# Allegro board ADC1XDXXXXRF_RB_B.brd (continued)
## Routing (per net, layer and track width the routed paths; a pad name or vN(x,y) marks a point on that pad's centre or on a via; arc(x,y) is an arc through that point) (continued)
TXD1: length 35.3
  TOP w0.14: J25.1 113.3,8.1 113.3,13.94 108.79,18.44 93.4,18.44 91.23,20.6 U2.52
USB_PWR: length 90.8
  TOP w0.305: v2(67.93,63.41) 67.93,62.38 U19.8
  TOP w0.508: C213.1 58.09,58.57 C214.1 ; C214.1 59.78,57.49 v2(59.78,57.49) ; C214.1 U19.4
  TOP w0.762: C213.1 58.08,7.78 58.78,7.09 66.77,7.09 71.56,11.88 71.56,14.55 70.83,15.28 J2.1
  BOTTOM w0.508: v2(67.93,63.41) 67.93,59.6 66.12,57.78 60.07,57.78 v2(59.78,57.49)
V_ADC: length 143.5
  TOP w0.457: J36.1 188.67,144.34 J23.3 ; J23.1 191.21,144.34 J34.1 ; J42.1 181.05,145.31 J23.9 ; J40.1 183.59,144.34 J23.7 ; J38.1 186.13,145.31 J23.5
  TOP w0.61: v1(183.36,83.31) 183.36,82.74 ; v1(189.71,83.31) 189.71,82.74 ; v1(176.05,83.18) 176.05,82.74
  TOP w0.762: L14.2 v2(160.99,167.36) C242.1 ; R58.1 191.41,82.74 v1(191.88,83.21) ; v2(160.99,162.75) 160.99,162.75 C244.1 ; C242.1 159.74,166.16 v2(159.73,166.17) ; C242.1 160.99,164.93 v2(160.99,164.93) 160.99,163.88 C244.1 ; C244.1 159.98,163.87 v2(159.98,163.88)
  PWR2 w0.356: J23.5 186.86,144.58 ; J23.5 186.86,146.05 ; J23.5 185.16,145.32 ; J23.5 185.39,146.05 ; J23.5 186.13,144.35 ; J23.5 185.39,144.58 ; J23.5 186.13,146.28 ; J23.5 187.09,145.32 ; 190.24,145.32 J23.1 ; J23.1 190.24,144.35 ; J23.1 192.17,146.28 ; J23.1 192.17,145.32 ; J23.1 191.21,144.35 ; J23.1 191.21,146.28 ; J23.1 190.24,146.28 ; J23.1 192.17,144.35 ; J23.9 181.78,146.05 ; J23.9 182.01,145.32 ; J23.9 180.31,146.05 ; J23.9 180.31,144.58 ; J23.9 181.78,144.58 ; J23.9 181.05,146.28 ; J23.9 181.05,144.35 ; J23.9 180.08,145.32 ; J23.7 183.59,146.28 ; J23.7 183.59,144.35 ; J23.7 184.32,146.05 ; J23.7 184.55,145.32 ; J23.7 182.85,146.05 ; J23.7 182.62,145.32 ; J23.7 184.32,144.58 ; J23.7 182.85,144.58 ; 187.93,144.58 J23.3 ; J23.3 188.67,146.28 ; J23.3 187.93,146.05 ; J23.3 188.67,144.35 ; J23.3 189.63,145.32 ; J23.3 187.7,145.32 ; J23.3 189.4,144.58 ; J23.3 189.4,146.05
  BOTTOM w0.254: 177.01,108.74 177.01,111.28 179.68,113.94 183.85,113.94 v1(185.34,115.44) 186.66,114.12 R222.2 186.66,109.12 186.39,108.84 186.39,107.87 R225.2 ; 177.01,108.74 R219.2 ; 177.01,108.74 R216.2 ; R210.2 178.2,83.18 v1(176.05,83.18) 175.52,83.18 R213.2 ; R204.2 188.45,82.04 v1(189.71,83.31) ; R207.2 184.38,86 184,85.62 184,83.94 v1(183.36,83.31)
  BOTTOM w0.406: C365.2 v1(185.34,115.44)
  BOTTOM w0.457: J23.7 183.59,145.31 J40.1 ; J23.3 188.67,145.31 J36.1 ; J38.1 186.13,145.31 J23.5 ; J35.1 191.21,145.31 J23.1 ; J42.1 181.05,145.31 J23.9
V_USI1: length 62.3
  BOTTOM w0.508: 155.26,165.22 155.26,165.23 158.82,168.79 165.63,168.79 183.18,186.34 186.77,186.34 189.79,189.36 J13.2 ; 155.26,165.22 155.26,156.7 J15.2 ; 155.26,165.22 J17.2
VCMO: length 135.7
  TOP w0.102: U1.C2 v1(198.57,86.67)
  SIG1 w0.152: J17.9 142.07,167.76 143.33,166.51 143.33,157.46 J15.9 ; v1(143.32,129.78) 145.79,127.31 v1(194.77,127.31)
  SIG3 w0.14: v1(143.32,129.78) 143.32,154.95 J15.9
  SIG3 w0.152: v1(198.57,86.67) 199.24,87.34 199.24,111.64 196.38,114.5 196.38,125.66 194.73,127.31 v1(194.77,127.31)
VIO_PRE: length 60.6
  TOP w0.305: U16.12 128.03,185.88 v2(128.01,185.85) ; L10.2 126.1,173.79 123.62,176.27 v2(123.62,185.85) 123.29,186.18 123.29,198.75 v2(124.21,199.66) 124.28,199.74 R106.1
  TOP w0.762: C194.1 140.22,178.98 141.96,180.72 C195.1 L2.1
  TOP w1.016: C194.1 140.23,176.66 140.23,174.9 139.12,173.79 L10.2
  BOTTOM w0.305: R105.1 v2(124.21,199.66) ; v2(128.01,185.85) v2(123.62,185.85)
WE_N: length 90.9
  TOP w0.102: U5.AA8 120.72,83.74 v1(120.71,83.74)
  TOP w0.14: v1(85.73,25.69) U2.41
  SIG1 w0.152: v1(85.73,25.69) 89.3,29.26 89.3,58.35 91.78,60.83 v1(91.78,81.22)
  BOTTOM w0.152: v1(120.71,83.74) 120.7,83.74 120.22,83.26 119.91,83.26 119.91,83.26 119.51,83.26 119.5,83.26 118.91,83.26 118.91,83.26 118.51,83.26 118.5,83.26 117.91,83.26 117.91,83.26 117.51,83.26 117.5,83.26 116.91,83.26 116.91,83.26 116.51,83.26 116.5,83.26 114.91,83.26 114.9,83.26 114.5,83.26 114.5,83.26 111.9,83.26 111.9,83.26 111.5,83.26 111.5,83.26 93.82,83.26 v1(91.78,81.22)
N16663533: length 50.8
  TOP w0.102: J28.3 192.81,3.71 ; J27.3 211.2,14.38
  TOP w0.14: 192.81,3.71 v1(192.81,5.64) ; 211.2,14.38 v1(209.27,14.38)
  SIG1 w0.152: v1(209.27,14.38) 182.64,14.38 182.38,14.12 182.38,12.53 182.66,12.26 192.16,12.26 192.81,11.61 v1(192.81,5.64)
N16663537: length 88.9
  TOP w0.102: J30.3 v1(159.44,5.64) ; J29.3 v1(209.27,43.77)
  SIG1 w0.102: v1(209.27,43.77) 209.27,38.46 208.91,38.1 205.68,38.1 203.62,36.04 203.62,21.84 202.22,20.44 168.87,20.44 165.21,16.78 165.21,5.84 165.01,5.64 v1(159.44,5.64)
N16663541: length 88.9
  TOP w0.102: J32.3 v1(171.25,5.64) ; J31.3 v1(209.27,31.95)
  SIG1 w0.102: v1(171.25,5.64) 165.63,5.64 165.41,5.85 165.41,16.7 168.96,20.24 202.31,20.24 203.82,21.75 203.82,35.96 205.76,37.9 208.9,37.9 209.27,37.53 v1(209.27,31.95)
N16721567: length 33.4
  TOP w0.14: J2.3 64.94,15.4 64.94,22.44 77.76,35.27 U2.18
N16721659: length 31.6
  TOP w0.14: U2.19 77.7,34.77 65.23,22.3 65.23,15.54 65.48,15.28 J2.2
N16722721: length 46.3
  BOTTOM w0.229: C69.2 76.63,5.51 ; C69.2 75.72,5.51 ; C69.2 77.55,5.51 ; C69.2 77.55,3.68 ; C69.2 76.63,3.68 ; C69.2 75.72,4.6 ; C69.2 77.55,4.6 ; C69.2 75.72,3.68 ; 75.72,6.07 R24.2 ; R24.2 75.72,6.99 ; R24.2 75.72,7.9 ; R24.2 77.55,7.9 ; R24.2 76.63,7.9 ; R24.2 77.55,6.99 ; R24.2 76.63,6.07 ; R24.2 77.55,6.07
  BOTTOM w0.356: 73.03,9.28 J2.6 ; J2.6 75.61,9.28 ; J2.6 75.61,11.86 ; J2.6 74.32,8.82 ; J2.6 73.03,11.86 ; J2.6 76.07,10.57 ; J2.6 72.57,10.57 ; J2.6 74.32,12.33 ; J2.5 64.03,10.57 ; J2.5 60.99,11.86 ; J2.5 62.28,8.82 ; J2.5 63.57,9.28 ; J2.5 62.28,12.33 ; J2.5 63.57,11.86 ; J2.5 60.53,10.57 ; J2.5 60.99,9.28
N16727306: length 5.7
  TOP w0.14: R23.1 77.25,26.77 U2.35
N16769321: length 22.8
  TOP w0.305: C164.1 108,195.87 108.11,195.76 U13.15
  TOP w0.762: L5.2 v2(102.59,184.32) 102.59,193.95 104.51,195.86 106.28,195.86 C164.1
  BOTTOM w0.762: D2.2 v2(102.59,184.32)
N16769692: length 3.6
  TOP w0.305: U13.2 108.11,187.6 107.71,187.2 106.74,187.2 106.58,187.04 C175.1
N16769839: length 5.7
  TOP w0.305: U13.1 104.97,188.63 R89.2 v2(104.97,187.31) R88.2
  BOTTOM w0.305: C178.1 v2(104.97,187.31)
N16770680: length 1.2
  TOP w0.305: U13.16 C164.2
N16772680: length 3.5
  TOP w0.305: U13.4 109.41,187.47 v1(109.72,187.16) C161.1
  BOTTOM w0.305: v1(109.72,187.16) 109.72,187.16 R82.1
N16798185: length 3.2
  TOP w0.305: C190.1 136.39,193.32 C188.2 134.87,193.32 U16.1
N16802160: length 30.8
  TOP w0.102: U5.G16 129.22,98.26 v1(129.72,98.75)
  TOP w0.14: v1(127.18,116.09) 126.72,116.56 117.85,116.56 117.46,116.17 117.46,115.4 R40.2
  SIG1 w0.152: v1(127.18,116.09) 129.29,113.98 129.29,107.5 128.22,106.43 128.22,102.31 129.21,101.32 129.21,99.26 v1(129.72,98.75)
N16802193: length 75.2
  TOP w0.102: U5.H13 v1(126.71,96.75) ; v1(165.48,58.07) 164.74,58.07 U8.6
  SIG2 w0.102: v1(165.48,58.07) 166.54,58.07 166.71,58.24 166.71,64.61 153.65,77.67 133.8,77.67 133.12,78.35 133.12,78.56 133.12,96.91 132.88,97.15 127.12,97.15 126.72,96.75 v1(126.71,96.75)
  BOTTOM w0.102: C75.2 166.62,58.48 166.47,58.33 165.74,58.33 v1(165.48,58.07)
N16802234: length 11.7
  TOP w0.102: U5.G14 127.22,98.26 v1(127.71,98.75)
  TOP w0.152: v1(127.74,106.97) R31.2
  SIG2 w0.152: v1(127.74,106.97) 128.21,106.49 128.21,99.25 v1(127.71,98.75)
N16802239: length 21.8
  TOP w0.102: v1(127.71,85.74) 127.22,86.24 U5.W14 ; U5.Y15 128.22,85.25 v1(128.71,85.74) 128.22,86.24 U5.W15
  TOP w0.14: R38.2 132.99,70.15 129.92,73.22 129.92,75.42 130.22,75.72 130.22,76.94 129.72,77.45 v1(129.72,77.45)
  SIG1 w0.152: v1(127.71,85.74) v1(128.71,85.74) 128.72,85.74 129.23,85.23 129.23,77.94 v1(129.72,77.45)
N16803121: length 3.8
  TOP w0.305: R103.1 130.23,195.82 C191.2 130.27,195.2 129.98,194.91 U16.6
N16805297: length 11.1
  TOP w0.305: U16.7 129.33,194.89 128.98,195.24 C191.1 128.85,195.91 C202.1 128.28,197.08 127.88,197.47 127.88,198.06 ; R106.2 127.81,199.74 v1(127.88,199.66) 127.88,198.06 127.88,198.06 ; 127.88,198.06 R107.2
  BOTTOM w0.305: R105.2 v1(127.88,199.66)
N16805320: length 1.8
  TOP w0.14: R53.1 Y2.3
N16807514: length 1.4
  TOP w0.305: C202.2 128.85,198.37 R103.2
N16809137: length 4.6
  TOP w0.305: U16.8 128.68,194.65 127.97,195.36 127.97,196.13 127.62,196.48 R108.2
N16815468: length 2.7
  TOP w0.305: U16.9 128.03,194.43 127.53,194.94 126.68,194.94 C206.1
N16819191: length 1.4
  TOP w0.305: U16.20 C189.1
N16819385: length 30.7
  TOP w0.305: 131.28,183.56 131.28,182.91 L10.1 ; 131.28,183.56 131.89,183.56 131.93,183.6 131.93,185.1 ; 131.28,183.56 U16.17 ; 131.93,185.1 134.38,185.1 134.66,185.38 C189.2 ; 131.93,185.1 U16.18
  TOP w0.762: v2(130.66,179.07) 130.66,182.27 L10.1 135.64,182.27 v2(136.73,181.18)
  BOTTOM w0.762: v2(130.66,179.07) 130.66,180.17 131.67,181.18 D4.2 v2(136.73,181.18)
N16821177: length 16.7
  TOP w0.305: v2(129.22,185.2) 129.98,185.96 U16.15 ; U16.16 130.63,185.2 v2(130.51,185.07)
  BOTTOM w0.508: v2(129.22,185.2) 129.2,185.2 128.59,184.58 127.69,184.58 126.84,183.73 126.84,181.25 D4.1 127.16,181.44 128.7,181.44 130.51,183.24 v2(130.51,185.07)
N16824930: length 1.4
  TOP w0.305: C205.1 125.98,187.38 U16.11
N16831687: length 18.3
  TOP w0.762: 143.38,184.82 147.82,184.82 152.48,180.15 C198.1 C196.1 U17.2
N16860475: length 1.5
  TOP w0.305: U18.1 C218.1
N16862731: length 5.5
  TOP w0.305: C212.1 R109.2 ; C212.1 v2(202.21,202.31) ; C212.1 U18.6
  BOTTOM w0.305: v2(202.21,202.31) C212.1
N16862763: length 10.5
  TOP w0.508: U18.5 202.19,200.11 C212.2 202.21,200.08 v2(202.21,198.46) C209.1
  TOP w0.762: L3.1 C209.1
  BOTTOM w0.508: R110.1 202.21,199.95 v2(202.21,198.46)
N16864683: length 9.2
  TOP w0.14: J163.3 R180.1
N16864708: length 2.8
  TOP w0.305: T2.4 200.9,126.09 201.05,125.93 C342.1
N16864710: length 2.8
  TOP w0.305: C341.1 202.06,125.93 202.22,126.09 T2.6
N16864734: length 11.4
  TOP w0.14: R180.2 201.56,130.51 C343.1
N16865152: length 13
  TOP w0.14: v1(194.51,159.79) 194.51,159.56 194.29,159.34 U12.30
  SIG1 w0.14: v1(194.51,159.79) 191.85,162.46 J158.2
N16865229: length 8.6
  TOP w0.14: J161.2 185.33,153.14 189.56,153.14 190.03,153.61 U12.10
N16865231: length 9.2
  TOP w0.14: J160.2 185.29,155.71 185.29,154.99 186.56,153.72 189.31,153.72 189.85,154.26 U12.9
N16865233: length 11.1
  TOP w0.14: J159.2 185.85,157.69 185.85,155.3 186.99,154.15 189.18,154.15 189.79,154.76 U12.8
N16865299: length 9
  TOP w0.14: J162.2 184.03,152.7 191.41,152.7 191.79,153.08 U12.11
N16865342: length 6.4
  TOP w0.14: C2_LF.1 197.43,157.56 196.64,156.76 U12.24 ; C2_LF.1 198.27,158.37 C1_LF.1 ; C2_LF.1 196.98,156.26 U12.23
N16865346: length 1.7
  TOP w0.14: R73.2 199.72,157.53 C2_LF.2 199.67,157.58 R2_LF.2
N16865743: length 6.8
  TOP w1.016: Y3.4 198.65,171.08 C138.2 C137.2 C240.1 R65.2
N16865780: length 1.5
  TOP w0.14: C321.2 199.49,154.42 R196.1 199.48,153.73 R195.2
N16865782: length 11.1
  TOP w0.14: R180.3 199.47,142.74 R197.1 199.47,152.05 R195.1
N16906306: length 4.3
  TOP w0.14: C139.1 R69.1 R68.1 193.83,166.65 R66.1
N16906312: length 2.1
  TOP w0.14: C139.2 193.79,160.98 U12.31
N16907733: length 22.6
  TOP w0.305: C165.1 113.34,195.87 111.5,195.87 111.36,195.73 U13.10
  TOP w0.762: C165.1 114.71,195.87 116.96,193.62 v2(116.96,184.56) 116.97,184.55 L6.1
  BOTTOM w0.762: v2(116.96,184.56) 117.01,184.51 D3.2
N16907748: length 2.4
  TOP w0.305: C176.1 111.44,187.14 111.36,187.22 111.36,188.63 U13.7
N16907762: length 4.6
  TOP w0.305: U13.8 112.01,188.63 R90.2 v2(113.33,187.31) R91.2
  BOTTOM w0.305: C179.1 v2(113.33,187.31)
N16907804: length 1.3
  TOP w0.305: U13.9 C165.2
N16911166: length 2.1
  TOP w0.254: C154.1 194.79,151.89 U12.17
N16911176: length 2.5
  TOP w0.14: U12.21 198.46,155.26 C321.1
N16911178: length 1.4
  TOP w0.254: C154.2 R78.2
N16911299: length 2.5
  TOP w0.254: C155.2 195.29,152.79 U12.18
N16911375: length 1.2
  TOP w0.254: C142.2 R70.1
N16911379: length 2.1
  TOP w0.254: U12.28 195.29,160.92 C142.1
N16911437: length 2.2
  TOP w0.254: U12.36 191.29,160.65 C143.1
N16911467: length 2.4
  TOP w0.14: U12.32 193.29,159.51 192.46,160.35 C140.2
N16911489: length 2.7
  TOP w0.254: C149.2 188.88,155.76 U12.6
  TOP w0.508: C149.2 v1(188.82,154.84)
N16911507: length 4.2
  TOP w0.254: U12.26 196.29,157.76 196.77,158.24 196.77,159.59 197.51,160.32 C147.2
N16911511: length 1.2
  TOP w0.254: C147.1 R71.1
N16915941: length 3.2
  TOP w0.14: Y3.3 R67.1 193.83,168.12 R66.2
N16917380: length 5.4
  TOP w0.14: v1(197.36,158.55) 197.18,158.37 197.18,157.91 196.53,157.26 U12.25
  BOTTOM w0.14: v1(197.36,158.55) v1(200.58,158.55)
N16922604: length 1.5
  TOP w0.14: T2.2 201.56,129.48 C343.2
N16954745: length 11.1
  TOP w0.508: C223.1 185.81,198.47 v2(185.82,198.48) C226.2 185.79,200.3 U20.5
  TOP w0.762: L12.1 C223.1
  BOTTOM w0.305: R118.1 185.82,200.12 v2(185.82,198.48)
N16954757: length 1.6
  TOP w0.305: U20.1 C227.1
N16954773: length 5.2
  TOP w0.305: U20.6 C226.1 185.82,202.43 v2(185.79,202.46) 185.8,202.47 R117.2
  BOTTOM w0.305: R118.2 185.79,201.57 v2(185.79,202.46)
N17041129: length 50.3
  TOP w0.14: v1(101.07,42.27) U2.99
  TOP w0.152: v1(122.08,16.05) R18.2
  TOP w0.203: R18.2 U3.3
  SIG1 w0.152: v1(122.08,16.05) 116.78,21.35 v1(116.78,42.27)
  SIG3 w0.152: v1(101.07,42.27) v1(116.78,42.27)
N17122999: length 2.7
  TOP w0.152: R20.2 U4.1
N17127467: length 3.4
  TOP w0.14: R16.1 102.4,35.27 U2.85
N17138281: length 37
  TOP w0.305: v2(84.72,39.29) 84.7,39.27 U2.10 ; U2.17 v2(84.72,35.77)
  TOP w1.016: L1.1 C64.1 75.07,50.51 v2(75.08,50.5)
  BOTTOM w0.508: v2(84.72,39.29) 85.79,39.29 C66.1 87.75,39.13 ; v2(84.72,35.77) 84.72,35.78 C65.1 87.51,35.78 87.75,36.02
  BOTTOM w1.016: v2(75.08,50.5) 76.34,49.24 81.34,49.24 87.75,42.82 87.75,36.02
N17209995: length 35.7
  BOTTOM w1.27: L9.2 66.26,182.06 85.39,201.19 J12.2
N17221364: length 40
  TOP w0.305: R99.2 62.18,175.26 72.08,175.26 74.63,177.82
  TOP w0.762: L4.1 C157.1
  TOP w1.524: C157.1 74.63,177.82 70.46,181.99 SW2.2
N17237535: length 25.4
  TOP w0.152: v1(103.05,33.63) 102.73,33.95 100.33,33.95 100.15,33.77 U2.82 ; v1(114.12,18.58) LD11.2
  BOTTOM w0.152: v1(103.05,33.63) 103.05,29.65 v1(114.12,18.58)
N17238039: length 2.1
  TOP w0.305: LD11.1 R142.1
N17247885: length 3.3
  TOP w0.305: R99.1 LD10.1
N17271500: length 1.5
  TOP w0.305: U15.1 C186.1
N17271514: length 5.2
  TOP w0.305: R97.2 R98.2 C185.1 U15.6
N17272516: length 7.4
  TOP w0.508: U22.5 170.5,200.14 C233.2
  TOP w0.635: C233.2 v2(170.52,198.99)
  TOP w0.762: v2(170.52,198.99) 170.19,198.99 169.69,198.49 C230.1 L13.1
  BOTTOM w0.508: v2(170.52,198.99) 170.52,199.99 R125.1
N17272520: length 1.5
  TOP w0.305: U22.1 C234.1
N17272540: length 5.5
  TOP w0.305: R124.2 v2(170.52,202.38) C233.1 U22.6
  BOTTOM w0.305: v2(170.52,202.38) 170.52,201.42 R125.2
N17383940: length 12.2
  TOP w0.14: U2.11 81.55,38.77 79.2,41.12 78.21,41.12 77.77,41.55 Y1.1
  TOP w0.152: C70.1 Y1.1
N17383990: length 12
  TOP w0.14: U2.12 81.62,38.27 79.07,40.82 78.21,40.82 77.77,40.39 Y1.2
  TOP w0.152: C71.1 Y1.2
N17384219: length 6.5
  TOP w0.14: TP2.1 82.98,50.25 U2.1
N17400918: length 1.5
  TOP w0.305: U23.20 95.05,159.89 R92.2
N17401691: length 3.5
  TOP w0.305: R93.2 92.79,168.15 91.65,167 91.65,165.82 91.64,165.82 U23.4
N17402468: length 1.6
  TOP w0.305: U23.1 93.59,165.83 C235.1
N17411980: length 1.5
  TOP w0.305: R93.1 92.79,171.83 C236.1
N17414023: length 3.3
  TOP w0.203: U3.4 SW1.1
N17421515: length 4.9
  TOP w0.305: C237.1 94.26,157.43 93.89,157.8 92.7,157.8 92.3,158.2 92.3,159.4 92.29,159.4 U23.18
N17425568: length 5.5
  TOP w0.305: U23.2 92.94,166.19 92.95,166.2 92.95,167.3 94.32,168.67 95.27,168.67 R94.2 R95.2
N17434478: length 43.4
  TOP w0.305: U23.8 89.04,166.23 89.05,166.23 89.05,167.95 ; 89.05,167.95 D1.2 ; 89.05,167.95 89.65,167.95 89.7,167.91 89.7,166.15 89.69,166.15 U23.7 ; v1(92.13,154.4) 92.13,154.41 C238.2 ; U23.13 89.04,159.07 89.05,159.06 89.05,158.74 v2(89.36,158.42) 89.7,158.75 89.7,159.3 89.69,159.3 U23.14
  TOP w0.762: 79.98,166.63 v2(79.98,166.6) L7.1 ; 79.98,166.63 D5.2 ; 79.98,166.63 82.9,166.63 D1.2
  BOTTOM w0.305: v1(92.13,154.4) 92.13,155.66 v2(89.36,158.42)
  BOTTOM w1.016: v2(89.36,158.42) 81.19,166.6 v2(79.98,166.6)
N17462336: length 40.7
  TOP w0.305: R94.1 96.1,167.25 96.47,166.88 96.47,152.81 95.35,151.69 88,151.69 86.23,153.46 79.99,153.46 L7.2
  TOP w0.762: L7.2 C239.1 C197.1 L8.1
N17658689: length 1
  TOP w0.102: U1.K2 v1(198.64,95.49)
N17658690: length 1.8
  TOP w0.102: v1(194.83,98.15) 194.87,98.15 U1.M4
  BOTTOM w0.305: C79.1 v1(194.83,98.15)
N17663170: length 1
  TOP w0.102: U1.L2 v1(198.64,96.76)
N17675090: length 1.8
  TOP w0.102: U1.J4 194.83,95.49 v1(194.83,95.53)
  BOTTOM w0.305: C72.1 v1(194.83,95.53)
N17676120: length 17.7
  TOP w0.102: 199.79,86 U1.B1
  TOP w0.14: TP1.1 206.58,73.56 206.58,79.22 199.79,86
N17676520: length 5.9
  TOP w0.102: v1(197.29,86.64) 196.71,87.23 196.71,87.25 196.7,87.25 U1.C3
  BOTTOM w0.102: R12.1 201.19,87.18 197.84,87.18 v1(197.29,86.64)
N17676524: length 5.8
  TOP w0.102: U1.D3 196.74,88.54 v1(197.34,87.95)
  BOTTOM w0.102: v1(197.34,87.95) 197.9,87.39 201.19,87.39 R12.2
N17676530: length 10.7
  TOP w0.102: R7.1 207.15,85.5 207.15,85.93 207.1,85.98 205.45,85.98 203.61,87.81 199.27,87.81 199.19,87.73 199.19,87.46 199.24,87.42 U1.C1
N17676534: length 10.8
  TOP w0.102: U1.D2 198.45,88.07 203.71,88.07 205.55,86.23 R7.2
N17751700: length 7.2
  BOTTOM w1.524: L9.4 J21.1
N17752133: length 44.8
  BOTTOM w1.524: J21.2 74.73,167.44 65.13,167.44 63.17,169.39 63.17,183.13 SW2.3
N17824195: length 30.1
  BOTTOM w1.27: L9.1 68.8,178.84 68.8,181.09 82.91,195.2 90.81,195.2
N17846912: length 1.8
  TOP w0.102: v1(197.35,104.42) 196.72,105.05 U1.U3
  BOTTOM w0.152: R9.2 197.41,104.36 v1(197.35,104.42)
N17848835: length 1.8
  TOP w0.102: U1.V3 196.72,106.32 v1(197.34,105.7)
  BOTTOM w0.152: v1(197.34,105.7) 197.43,105.78 R25.2
N17849798: length 2.3
  TOP w0.102: U1.Y3 196.69,108.86 v1(196.1,109.46)
  BOTTOM w0.152: v1(196.1,109.46) 196.11,109.46 196.51,109.85 196.51,110.68 R2.2
N17850762: length 3.8
  TOP w0.102: U1.W4 195.45,107.59 v1(196.03,108.18)
  BOTTOM w0.152: R3.2 195.39,110.32 195.39,108.82 v1(196.03,108.18)
N17851727: length 1.7
  TOP w0.102: U1.B3 196.11,86.6 v1(196.09,86.6)
  BOTTOM w0.14: R4.2 196.1,86.6 v1(196.09,86.6)
N17852693: length 5.9
  TOP w0.102: v1(196.06,106.95) 195.44,106.32 U1.V4
  BOTTOM w0.14: 194.17,109.25 195.19,108.22 195.2,108.22 196.06,107.36 v1(196.06,106.95)
  BOTTOM w0.152: R5.2 193.44,110.73 193.44,110.17 193.56,110.05 193.86,110.05 194.17,109.74 194.17,109.25
N17853660: length 7.9
  TOP w0.102: U1.V5 194.18,106.32 v1(194.76,106.91)
  SIG1 w0.152: v1(191.86,111.25) 192.94,111.25 194.76,109.43 v1(194.76,106.91)
  BOTTOM w0.14: v1(191.86,111.25) R6.2
N17854628: length 3.1
  TOP w0.102: U1.A4 195.43,84.73 v1(196.09,84.07)
  BOTTOM w0.14: v1(196.09,84.07) 196.09,83.34 196.46,82.96 197.31,82.96 R8.2
N18005197: length 2.3
  TOP w0.762: L14.1 J22.2
N18092594: length 7.2
  TOP w0.14: U2.113 92.23,52.67 92.2,52.7
N18092628: length 7.6
  TOP w0.14: 93.7,52.7 93.7,52.7 93.7,52.01 92.73,51.04 U2.112
N18102458: length 4.3
  TOP w0.14: R17.1 102.4,31.6 102.07,31.27 U2.77
N18106734: length 13.2
  TOP w0.305: 160.15,180.92 161.11,180.92 v2(161.12,180.91)
  TOP w0.762: 160.15,180.91 C201.1 160.15,178.56 160.99,177.72 C248.1 J22.1 ; 160.15,180.91 U17.4 ; 160.15,180.91 v2(161.12,180.91) C247.1
  BOTTOM w0.508: v2(161.12,180.91) 161.38,181.17 161.9,181.17 R149.1
N18113304: length 7.2
  TOP w0.762: 162.99,182.98 161.85,182.98 U17.5 v2(162.99,183.14) 162.99,182.98 ; 162.99,182.98 162.99,181.84 163.52,181.32 C247.2
  BOTTOM w0.508: 162.99,182.74 R149.2 ; 162.99,182.74 163.87,182.74 163.96,182.65 ; 162.99,182.74 v2(162.99,183.14)
N18167238: length 17.1
  TOP w0.508: 69.99,56.85 C219.2 69.96,58.57 U19.5 67.93,56.85 ; 69.99,56.85 67.93,56.85 ; 69.99,56.85 72.91,56.85 73.09,57.03 R112.1 ; 67.93,56.85 C215.1
  TOP w0.762: C215.1 66,53.75 L11.1
N18167362: length 1.6
  TOP w0.305: U19.1 C220.1
N18167368: length 5.2
  TOP w0.508: U19.6 C219.1 R111.2 R112.2
N18175634: length 19.7
  TOP w0.305: U29.5 81.48,192.23 C267.1 v2(81.48,189.73) 81.48,188.58 U21.1 79.4,188.57 79.14,188.32 79.14,186.92 79.4,186.66 U21.3
  BOTTOM w0.305: R122.2 R121.2 R120.2 84.96,189.73 v2(81.48,189.73)
N18175719: length 5.6
  TOP w0.305: U21.6 85.16,188.57 86.75,190.16 89.01,190.16 J14.1
N18175721: length 5
  TOP w0.305: J14.3 89.01,187.62 U21.5
N18175723: length 5.6
  TOP w0.305: U21.4 85.43,186.66 87.01,185.08 J14.5
N18175776: length 1.6
  TOP w0.305: C266.1 81.47,194.84 U29.4
N18581058: length 6.4
  BOTTOM w0.635: J157.1 21.03,122.07 FMC.K40 FMC.J39
N18581183: length 15.4
  BOTTOM w0.635: FMC.G39 FMC.H40 16.51,121.13 ; 16.51,121.13 15.01,121.13 FMC.F40 FMC.E39 ; 16.51,121.13 17.55,121.13 21.03,124.61 J157.2
N19099019: length 2.7
  TOP w0.102: v1(194.16,82.89) 194.16,82.9 U1.A5
  BOTTOM w0.14: v1(194.16,82.89) R127.2
N19100077: length 2
  TOP w0.102: U1.D6 193.51,89.17 v1(193.51,89.22)
  BOTTOM w0.152: R128.2 193.51,89.83 v1(193.51,89.22)
N19255100: length 5.9
  TOP w0.14: U24.2 206.94,129.61 207.18,129.84 J19.3
N19265006: length 2
  TOP w0.152: U24.7 206.94,123.31 v1(207.34,122.91)
  BOTTOM w0.102: v1(207.34,122.91) R131.1
N19266083: length 2
  TOP w0.152: v1(205.89,122.91) 206.29,123.31 U24.6
  BOTTOM w0.102: v1(205.89,122.91) R129.1
N19380996: length 2.6
  TOP w0.14: U24.3 206.29,129.76 206.19,129.86 205.76,129.86 205.64,129.75 U24.4
N20455301: length 6.9
  TOP w0.14: R83.3 149.17,40.23 150.29,41.35 U14.12
N20455532: length 6.7
  TOP w0.14: R83.1 149.35,43.64 150.14,42.85 U14.9
N21058732: length 102.6
  TOP w0.102: v1(132.72,80.74) 132.22,81.24 U5.AD19
  TOP w0.14: R44.1 168.52,132.36 v1(168.52,131.88)
  SIG1 w0.152: v1(133.95,75.89) v1(161.2,75.89)
  SIG3 w0.152: v1(132.72,80.74) 132.7,80.74 132.21,80.25 132.21,77.62 v1(133.95,75.89)
  BOTTOM w0.14: v1(161.2,75.89) 161.2,116.37 168.52,123.69 v1(168.52,131.88)
N21059382: length 97.3
  TOP w0.102: U5.AC19 132.22,82.24 v1(132.72,81.74)
  TOP w0.14: v1(167.75,131.11) 167.75,134.14 R45.1
  SIG1 w0.152: v1(160.29,77.27) 140.27,77.27 136.29,81.24 133.22,81.24 132.83,81.63 132.83,81.63 v1(132.72,81.74)
  BOTTOM w0.14: v1(160.29,77.27) 160.29,97.36 160.73,97.81 160.73,99.01 160.29,99.45 160.29,116.53 167.75,123.99 v1(167.75,131.11)
N21060033: length 102
  TOP w0.102: v1(132.72,83.74) 132.22,84.24 U5.AA19
  TOP w0.14: v1(166.99,131.88) 166.99,135.92 R46.1
  SIG1 w0.152: v1(159.43,76.34) 134.2,76.34 132.22,78.32 132.22,83.25 v1(132.72,83.74)
  BOTTOM w0.14: v1(159.43,76.34) 159.43,97.06 158.69,97.81 158.69,98.7 159.43,99.45 159.43,116.73 166.99,124.29 v1(166.99,131.88)
N21060685: length 98.7
  TOP w0.102: U5.AA20 133.22,84.24 v1(133.72,83.74)
  TOP w0.14: v1(166.22,131.11) 166.22,137.69 R26.1
  SIG1 w0.152: v1(134.43,76.81) v1(158.62,76.81)
  SIG3 w0.152: v1(134.43,76.81) 133.23,78.02 133.23,83.26 133.71,83.74 v1(133.72,83.74)
  BOTTOM w0.14: v1(166.22,131.11) 166.22,124.59 158.62,116.99 158.62,99.39 158.24,99.02 158.24,97.49 158.62,97.12 v1(158.62,76.81)
N21061338: length 104.3
  TOP w0.102: v1(130.72,84.74) 130.22,85.24 U5.Y17
  TOP w0.14: v1(165.46,131.88) 165.46,138.51 R27.1
  SIG1 w0.152: v1(130.73,76.69) 132.44,74.97 v1(157.78,74.97)
  SIG3 w0.152: v1(130.73,76.69) 130.22,77.2 130.22,84.25 v1(130.72,84.74)
  BOTTOM w0.14: v1(157.78,74.97) 157.78,117.22 165.46,124.89 v1(165.46,131.88)
N21061992: length 101.8
  TOP w0.102: U5.AA17 130.22,84.24 v1(130.72,83.74)
  TOP w0.14: v1(164.7,131.11) 164.7,136.73 R28.1
  SIG1 w0.152: v1(157.1,75.43) 132.81,75.43 v1(131.72,76.52)
  SIG3 w0.152: v1(131.72,76.52) 131.22,77.01 131.22,83.23 130.72,83.73 v1(130.72,83.74)
  BOTTOM w0.14: v1(164.7,131.11) 164.7,125.2 157.1,117.6 v1(157.1,75.43)
N21062647: length 92.6
  TOP w0.102: U5.AB20 133.22,83.24 v1(133.72,82.74)
  TOP w0.14: v1(163.93,131.88) 163.93,134.96 R113.1
  SIG3 w0.152: v1(156.29,78.17) 135.23,78.17 135.09,78.31 135.09,78.31 134.22,79.18 134.22,82.25 133.73,82.74 v1(133.72,82.74)
  BOTTOM w0.14: v1(163.93,131.88) 163.93,125.5 156.29,117.86 v1(156.29,78.17)
N21063303: length 86.7
  TOP w0.102: v1(133.72,81.74) 133.22,82.24 U5.AC20
  TOP w0.14: R114.1 155.56,137.19 v1(155.56,126.5)
  SIG1 w0.152: v1(133.72,81.74) 133.73,81.74 134.23,82.24 138.12,82.24 142.65,77.72 v1(155.57,77.72)
  BOTTOM w0.14: v1(155.56,126.5) 155.57,126.49 v1(155.57,77.72)
N21827542: length 1.7
  TOP w0.102: R136.1 201.52,179.62 201.78,179.87 U25.7
N21827567: length 1.7
  TOP w0.102: U25.6 201.73,180.52 201.52,180.73 201.52,180.97 201.53,180.97 R134.1
N21827581: length 4.2
  TOP w0.14: U25.2 207.81,179.87 J26.3
N21832116: length 2.4
  TOP w0.203: U25.3 207.8,180.52 208.64,180.52 208.74,180.62 208.74,181.03 208.6,181.17 U25.4
N21933562: length 3.7
  TOP w0.14: R126.1 157.58,58.98 159.11,58.98 160.02,58.07 U8.9
N23828730: length 11.2
  TOP w0.102: 124.71,80.75 125.21,81.24 U5.AD12
  TOP w0.14: 124.71,80.75 124.71,70.26 R53.2
N200444310: length 2.4
  TOP w0.203: DCLK_LOCKED.1 v4(201.68,46.06)
  BOTTOM w0.203: v4(201.68,46.06) R54.1
N200444470: length 2.3
  TOP w0.203: ECM_ENABLED.1 v4(201.63,31.81)
  BOTTOM w0.203: v4(201.63,31.81) R55.1
N200445120: length 2.3
  TOP w0.203: v4(201.63,41.97) TRIGGER_ARMED.1
  BOTTOM w0.203: R49.1 v4(201.63,41.97)
N200445200: length 2.3
  TOP w0.203: v4(201.63,37.9) ADC_CALIBRATION.1
  BOTTOM w0.203: R48.1 v4(201.63,37.9)
N200445280: length 2.3
  TOP w0.203: OVER-RANGE_Q-CH.1 v4(201.63,44)
  BOTTOM w0.203: v4(201.63,44) R51.1
N200445360: length 2.3
  TOP w0.203: OVER-RANGE_I-CH.1 v4(201.63,35.87)
  BOTTOM w0.203: v4(201.63,35.87) R50.1
N200445600: length 2.3
  TOP w0.203: ADC_POWER.1 v4(201.63,39.93)
  BOTTOM w0.203: v4(201.63,39.93) R47.1
N200446320: length 2.3
  TOP w0.203: v4(201.63,33.84) FPGA_OPERATIONAL.1
  BOTTOM w0.203: R52.1 v4(201.63,33.84)
N210916850: length 2.3
  TOP w0.203: v1(201.64,29.79) 201.63,29.78 RCOUT1/2_ENABLED.1
  BOTTOM w0.203: R115.1 200.75,29.79 v1(201.64,29.79)
N1739169316: length 3.4
  TOP w0.305: C238.1 92.12,156.72 92.12,157.5 91.64,157.98 U23.17

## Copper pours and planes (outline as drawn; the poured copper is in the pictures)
1V2VCC_INT on PWR1: 53.06,150.34 51.99,149.28 51.99,136.12 52.77,135.34 88.1,135.34 121.09,102.35 121.09,86.22 129.9,86.22 132.49,88.81 132.49,96.06 131.36,97.19 130.2,97.19 124.26,103.13 124.26,122.48 96.94,149.79 96.94,149.62 96.22,150.34
1V8IO on PWR1: 124.9,176.02 124.9,108.01 133.16,99.76 133.16,89.03 130.13,86 129.18,86 129.18,81.68 134.61,76.24 134.61,63.78 140.47,57.93 140.47,54.47 141.38,53.56 144.84,53.56 153.45,44.95 156.05,44.95 157.21,43.78 157.21,41.58 156.29,40.65 153.5,40.65 153.01,40.17 153.01,39.05 153.43,38.64 171.21,38.64 171.62,39.05 172.26,39.05 172.26,39.05 178.25,39.05 179.01,39.81 179.01,41.09 178.62,41.48 164.7,41.48 164.16,42.02 164.16,47.08 164.03,47.21 153.91,47.21 145.99,55.13 145.99,56.63 144.69,57.93 143.19,57.93 139.57,61.55 139.57,76.64 169.42,76.64 172.66,79.88 172.66,113.93 169.6,116.99 144.83,116.99 143.57,118.26 143.57,139.88 147.32,143.63 149.72,143.63 152.03,141.32 176.09,141.32 178.94,144.17 178.94,153.01 177.82,154.13 138.94,154.13 137.53,155.53 137.53,175.94 137.45,176.02
1V9AC on PWR2: 194.44,122.56 194.44,102.23 194.81,101.87 197.26,101.87 197.43,102.04 197.43,130.47 192.9,135 192.9,143.71 192.55,144.06 187.38,144.06 187.38,129.63
1V9ANA on PWR1: 188.61,144.06 188.61,132.39 200.56,120.43 200.56,112.21 202.11,110.66 202.11,102.87 200.54,101.3 199.87,101.3 199.22,101.95 194.54,101.95 193.99,101.4 193.99,100.55 194.53,100 195.3,100 195.4,99.9 195.4,94.41 194.1,93.11 194.1,92.5 195.11,91.49 200.22,91.49 201.15,90.57 201.15,79.77 199.25,77.87 193.13,77.87 191.71,79.29 191.71,86.95 190.7,87.97 190.34,87.97 188.76,89.54 188.76,104.46 189.44,105.14 190.95,105.14 191.74,105.93 191.74,122.27 185.09,128.91 185.09,143.67 185.48,144.06
1V9AT on PWR1: 208.83,77.5 201.36,84.98 201.36,90.96 200.64,91.67 195.39,91.67 194.33,92.73 194.33,93.12 195.63,94.42 195.63,100 195.47,100.16 194.64,100.16 194.31,100.5 194.31,101.16 194.9,101.75 199.19,101.75 199.86,101.08 201.11,101.08 206.21,106.18 206.21,115 188.76,132.45 188.76,144.05 192.57,144.05 192.73,143.88 192.73,136.16 207.7,121.19 214.27,121.19 214.27,115.63 209.3,115.63 209.3,113.41 214.27,113.41 214.27,103.81 209.3,103.81 209.3,101.6 214.27,101.6 214.27,92 209.3,92 209.3,89.79 214.27,89.79 214.27,80.17 209.3,80.17 209.3,78.01 214.27,78.01 214.27,44.87 209.3,44.87 209.3,42.66 214.27,42.66 214.27,33.06 209.3,33.06 209.3,30.85 214.27,30.85 214.27,15.48 209.3,15.48 209.3,13.27 214.27,13.27 214.27,3.55 211.99,1.27 193.91,1.27 193.91,5.61 191.7,5.61 191.7,1.27 172.36,1.27 172.36,5.61 170.15,5.61 170.15,1.27 160.55,1.27 160.55,5.61 158.34,5.61 158.34,1.27 150.88,1.27 150.32,1.83 150.32,21.49 153.59,24.76 200.94,24.76 202.28,26.09 202.28,66.29 208.83,72.85
1V9DR on PWR1: 182.11,143.8 182.11,124.45 189.14,117.42 189.14,107.74 186.35,104.95 186.35,88.34 188.77,85.92 188.77,79.95 185.46,76.64 176.5,76.64 173.23,79.91 173.23,115.3 170.3,118.22 147.92,118.22 146.62,119.52 146.62,141.47 147.98,142.82 149.65,142.82 151.87,140.6 176.22,140.6 179.74,144.12 181.79,144.12
1V9ENC on PWR1: 184.93,143.75 184.93,128.6 191.48,122.05 191.48,106.16 190.69,105.37 189.43,105.37 188.54,104.48 188.54,89.52 190.31,87.76 190.58,87.76 191.49,86.85 191.49,82.32 191.27,82.1 189.31,82.1 188.95,82.47 188.95,86.01 186.51,88.45 186.51,104.87 189.42,107.78 189.42,117.56 182.3,124.68 182.3,144.05 184.63,144.05
2V5IO on PWR2: 110.11,176.19 110.11,120.97 122.35,108.74 122.35,105.16 122.59,104.82 122.59,102.64 123.16,102.64 123.19,98.15 123.78,97.57 123.78,96.65 123.96,96.47 124.96,96.47 125.14,96.65 128.45,96.65 128.76,96.33 128.76,95.33 128.23,94.81 123.71,94.81 122.99,95.53 120.95,95.53 120.95,104.01 119.13,104.01 119.13,103.73 117.96,103.73 117.96,104.01 117.45,104.01 117.45,103.73 114.15,103.73 113.44,104.44 110.06,104.44 110.06,86.86 115.71,86.86 115.71,86.77 120.33,86.77 122.21,88.66 126.78,88.66 127.45,87.99 127.45,87.22 127.07,86.83 124.49,86.83 124.33,87 123.62,87 123.14,86.51 123.14,82.23 123.53,81.84 129.35,81.84 129.67,81.52 129.56,81.4 129.56,76.54 135.81,70.29 135.81,62.55 136.15,62.21 150.08,62.21 151.19,61.09 151.19,54.69 150.29,53.78 138.31,53.78 137.87,53.34 137.87,45.82 135.49,43.45 135.49,21.89 151.46,21.89 151.56,21.99 151.56,30.73 142.87,39.42 142.87,46.21 146.85,50.19 154.67,50.19 156.99,52.52 156.99,73.98 159.77,76.76 188.42,76.76 188.42,111.33 182.88,116.86 131.06,116.86 123.98,123.93 123.98,176.19
3V0PLL on PWR2: 167.67,195.3 167.67,173.63 193.37,147.93 205.21,147.93 205.21,171.32 197.54,178.99 183.98,178.99 178.52,184.44 178.52,194.4 177.38,195.54 167.92,195.54
3V3IO on PWR2: outline of 106 points within 1.27,1.27 214.29,176.17
3V3USB on PWR1: 78.77,1.27 78.77,19.25 67.61,19.25 67.61,18.36 77.88,18.36 77.88,1.27 59.89,1.27 59.89,18.36 62.56,18.36 62.56,19.25 59,19.25 59,1.27 52.07,1.27 52.07,64.51 52.57,65.01 113.89,65.01 115.88,63.01 115.88,35.93 117.17,34.64 123.94,34.64 126.97,31.61 126.97,1.37 126.87,1.27
3V3USI1 on PWR2: 180.93,195.69 180.78,195.69 179.7,194.61 179.7,184.71 184.29,180.12 197.52,180.12 206.15,171.49 206.15,132.42 203.94,130.21 203.94,122.38 206.63,119.68 206.63,75.2 210.67,71.16 210.67,50.79 210.49,50.61 182.46,50.61 175.36,57.71 169.21,57.71 168.73,57.22 165.06,57.22 164.68,57.61 164.68,59.69 163.4,60.98 158.43,60.98 157.45,59.99 157.45,49.92 158.86,48.5 213.42,48.5 214.29,49.37 214.29,185.48 212.57,187.2 189.42,187.2 188.46,188.16 188.46,193.15 185.89,195.71 180.94,195.71
5V0USI1 on PWR2: 191.06,195.08 191.06,188.44 191.65,187.86 205.33,187.86 206.04,188.57 206.04,194.79 205,195.84 191.83,195.84
GND on TOP, BOTTOM: 151.54,186.06 151.54,197.23 165.66,197.23 165.66,186.06
GND on BOTTOM: 214.29,185.52 209.3,185.52 209.3,174.17 214.29,174.17
GND on BOTTOM: 88.49,161.29 88.49,164.44 92.84,164.44 92.84,161.29
GND on BOTTOM: 198.5,0.59 198.5,5.59 187.15,5.59 187.15,0.59
GND on BOTTOM: 214.29,135.51 209.3,135.51 209.3,124.16 214.29,124.16
GND on BOTTOM: 128.14,188.77 128.14,191.92 132.48,191.92 132.48,188.77
GND on BOTTOM: 176.94,0.59 176.94,5.59 165.59,5.59 165.59,0.59
GND on BOTTOM: 214.29,108.33 209.3,108.33 209.3,96.98 214.29,96.98
GND on BOTTOM: 214.29,20.04 209.3,20.04 209.3,8.69 214.29,8.69
GND on BOTTOM: 214.29,147.62 209.3,147.62 209.3,136.27 214.29,136.27
GND on BOTTOM: 214.29,96.55 209.3,96.55 209.3,85.19 214.29,85.19
GND on BOTTOM: 165.13,0.59 165.13,5.59 153.77,5.59 153.77,0.59
GND on BOTTOM: 214.29,120.14 209.3,120.14 209.3,108.79 214.29,108.79
GND on BOTTOM: 164.36,200.84 164.36,203.27 166.8,203.27 166.8,200.84
GND on BOTTOM: 214.29,84.71 209.3,84.71 209.3,73.36 214.29,73.36
GND on BOTTOM: 214.32,37.62 209.32,37.62 209.32,26.26 214.32,26.26
GND on BOTTOM: 196.18,200.79 196.18,203.23 198.62,203.23 198.62,200.79
GND on BOTTOM: 214.32,49.45 209.32,49.45 209.32,38.1 214.32,38.1
GND on BOTTOM: 179.66,200.99 179.66,203.42 182.1,203.42 182.1,200.99
GND on BOTTOM: 108.16,190.03 108.16,193.18 111.31,193.18 111.31,190.03
GND on GND1: 52.07,1.27 52.07,62.56 1.27,62.56 1.27,128.09 52.07,128.09 52.07,208.28 214.29,208.28 214.29,143.05 209.32,143.05 209.32,140.84 214.29,140.84 214.29,130.95 209.32,130.95 209.32,128.74 214.29,128.74 214.29,115.63 209.3,115.63 209.3,113.41 214.29,113.41 214.29,103.81 209.3,103.81 209.3,101.6 214.29,101.6 214.29,92 209.3,92 209.3,89.79 214.29,89.79 214.29,80.17 209.3,80.17 209.3,78.01 214.29,78.01 214.29,44.87 209.3,44.87 209.3,42.66 214.29,42.66 214.29,33.06 209.3,33.06 209.3,30.85 214.29,30.85 214.29,15.48 209.3,15.48 209.3,13.27 214.29,13.27 214.29,1.27 193.91,1.27 193.91,5.61 191.7,5.61 191.7,1.27 172.36,1.27 172.36,5.61 170.15,5.61 170.15,1.27 160.55,1.27 160.55,5.61 158.34,5.61 158.34,1.27 78.77,1.27 78.77,19.25 67.61,19.25 67.61,18.36 77.88,18.36 77.88,1.27 59.89,1.27 59.89,18.36 62.56,18.36 62.56,19.25 59,19.25 59,1.27
GND on PWR1: 1.27,83.21 1.27,118.47 103.86,118.47 117.35,104.98 117.41,104.46 117.93,104.4 120.83,101.5 120.83,85.14 95.81,85.14 95.81,85.67 83.44,85.67 83.44,83.21
GND on GND2: 52.07,208.28 52.07,128.09 1.27,128.09 1.27,62.56 52.07,62.56 52.07,1.27 59,1.27 59,19.25 62.56,19.25 62.56,18.36 59.89,18.36 59.89,1.27 77.88,1.27 77.88,18.36 67.61,18.36 67.61,19.25 78.77,19.25 78.77,1.27 158.34,1.27 158.34,5.61 160.55,5.61 160.55,1.27 170.15,1.27 170.15,5.61 172.36,5.61 172.36,1.27 191.7,1.27 191.7,5.61 193.91,5.61 193.91,1.27 214.29,1.27 214.29,13.27 209.3,13.27 209.3,15.48 214.29,15.48 214.29,30.85 209.3,30.85 209.3,33.06 214.29,33.06 214.29,42.66 209.3,42.66 209.3,44.87 214.29,44.87 214.29,78.01 209.3,78.01 209.3,80.17 214.29,80.17 214.29,89.79 209.3,89.79 209.3,92 214.29,92 214.29,101.6 209.3,101.6 209.3,103.81 214.29,103.81 214.29,113.41 209.3,113.41 209.3,115.63 214.29,115.63 214.29,128.74 209.32,128.74 209.32,130.95 214.29,130.95 214.29,140.84 209.32,140.84 209.32,143.05 214.29,143.05 214.29,208.28
GND on GND3: 52.07,208.28 52.07,128.09 1.27,128.09 1.27,62.56 52.07,62.56 52.07,1.27 59,1.27 59,19.25 62.56,19.25 62.56,18.36 59.89,18.36 59.89,1.27 77.88,1.27 77.88,18.36 67.61,18.36 67.61,19.25 78.77,19.25 78.77,1.27 214.29,1.27 214.29,208.28
VIN on PWR1: 52.07,208.28 52.07,151.62 52.81,150.88 95.15,150.88 96.85,152.58 96.85,176.27 98.13,177.55 152.25,177.55 154.28,175.52 164.18,175.52 166.8,178.14 166.8,195.32 167.62,196.15 206.67,196.15 206.67,208.28
FMC_PG_M2C on BOTTOM (solid shape): 53.86,67.66 53.87,67.61 53.86,67.57 53.16,66.87 52.38,67.61 53.16,68.36
Net_23 on TOP (solid shape): outline of 518 points within 43.41,114.33 54.23,124.85
Net_24 on TOP (solid shape): 51.36,124.2 51.32,124.2 51.32,123.98 51.28,123.98 51.28,123.76 51.23,123.76 51.23,123.55 51.19,123.55 51.19,123.33 51.15,123.33 51.15,123.28 50.19,123.28 50.19,123.5 50.23,123.5 50.23,123.72 50.28,123.72 50.28,123.94 50.32,123.94 50.32,124.15 50.36,124.15 50.36,124.24 51.36,124.24
Net_25 on TOP (solid shape): outline of 84 points within 49.23,118.42 51.06,122.85
Net_26 on TOP (solid shape): outline of 90 points within 55.8,118.37 59.93,122.85
Net_27 on TOP (solid shape): outline of 114 points within 59.19,118.37 62.23,121.76
Net_28 on TOP (solid shape): outline of 116 points within 80.53,113.2 83.62,116.59
Net_29 on TOP (solid shape): outline of 588 points within 62.19,118.37 69.27,121.76
Net_30 on TOP (solid shape): outline of 288 points within 69.19,118.33 71.97,121.85
Net_31 on TOP (solid shape): outline of 290 points within 62.53,113.11 65.36,116.63
Net_32 on TOP (solid shape): outline of 292 points within 90.62,113.11 93.4,116.63
Net_33 on TOP (solid shape): 58.62,117.55 58.54,117.55 58.54,117.5 58.45,117.5 58.45,117.46 58.4,117.46 58.4,117.42 58.36,117.42 58.36,117.37 58.32,117.37 58.32,117.29 58.27,117.29 58.27,113.5 58.32,113.5 58.32,113.42 58.36,113.42 58.36,113.37 58.45,113.37 58.45,113.33 58.54,113.33 58.54,113.29 58.62,113.29 58.62,113.2 57.1,113.2 57.1,113.29 57.23,113.29 57.23,113.33 57.32,113.33 57.32,113.37 57.36,113.37 57.36,113.42 57.4,113.42 57.4,113.46 57.45,113.46 57.45,113.55 57.49,113.55 57.49,117.29 57.45,117.29 57.45,117.37 57.4,117.37 57.4,117.42 57.36,117.42 57.36,117.46 57.32,117.46 57.32,117.5 57.19,117.5 57.19,117.55 57.1,117.55 57.1,117.63 58.62,117.63
Net_34 on TOP (solid shape): outline of 246 points within 58.93,113.16 62.4,116.59
Net_35 on TOP (solid shape): outline of 244 points within 83.7,113.16 87.18,116.59
Net_36 on TOP (solid shape): outline of 106 points within 65.32,113.2 68.53,116.59
Net_37 on TOP (solid shape): outline of 100 points within 87.27,113.2 90.48,116.59
Net_38 on TOP (solid shape): outline of 240 points within 68.62,113.11 72.36,116.59
Net_39 on TOP (solid shape): outline of 146 points within 72.05,113.11 75.66,116.59
Net_40 on TOP (solid shape): outline of 282 points within 75.88,113.11 80.23,116.59
V_ADC on PWR2: 165.59,172.91 157.4,172.91 156.96,172.48 156.96,163.28 168.93,151.32 174.34,151.32 178.36,147.29 178.36,121.97 191.38,108.95 191.38,78.08 194.53,74.94 194.53,67.13 199.33,62.32 199.33,52.85 200.24,51.95 210.06,51.95 210.06,56.68 200.55,66.19 200.55,100.93 199.77,101.7 194.69,101.7 194.2,102.19 194.2,122.45 187.2,129.45 187.2,144.23 192.53,144.23 192.7,144.41 192.7,146.87 192.35,147.22 192.25,147.22 166.57,172.92
N16722721 on BOTTOM: 77.87,1.27 77.87,14.28 74.37,14.28 70.59,10.51 65.55,10.51 62.75,13.31 62.75,13.31 59.89,13.31 59.89,1.27

Small or netless copper shapes (teardrops, artwork), in the pictures only: 98 on TOP, 13 on BOTTOM, 14 on SIG1, 22 on SIG2, 24 on SIG3

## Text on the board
BOTTOM: L10_BOTTOM
Board Geometry/Soldermask Bottom: SOLDERMASK, BOTTOM SIDE
Ref Des/Silkscreen Bottom: DCLK | RST- | RST+ | MADE IN U.S. | UL 94V-0 | SILKSCREEN, BOTTOM SIDE
User.Comments: SOLDERMASK, TOPSIDE
Board Geometry/Outline: LAYER INDICATOR
TOP: L1_TOP
Ref Des/Silkscreen Top: 1 | CY_CLK | ENABLE1 | ENABLE3 | ENABLE2 | TXD0 | RXD0 | TXD1 | GND | RXD1 | A | B | RESET | 10 | 9 | 2 | VBG | 3V3USB | TEST4N | TEST4P | TEST3N | TEST3P | TEST2N | TEST2P | TEST1N | TEST1P | JP_5 | JP_4 | V4_TDI | JP_3 | V4_TCK | JP_2 | V4_TDO | JP_1 | V4_TMS | 3V3IO | CAL | NDM | TPM | CALDLY | DDRPHASE | FSR | DES | ECE | PDQ | PDI | 1V9DR | 1V9ENC | 1V9ANA | 3V3USI1 | 1V9AC | V_USI1 | 1V9AT | 5V0USI1 | VINI+ | VINQ- | VINI- | VINQ+ | SDI 9 | SCS | SCLK | SDO | 1V9ANA 1 | ADC10D1500RB | ADC12D1600RB | ADC12D1800RB | ADC12D800RFRB | ADC12D1600RFRB | ADC12D1800RFRB | ADC12D2000RFRB | FMC_VIO_B_M2C | FMC_VADJ | SV600863- | PCB REV B | Gigasample Reference Board | ADC1xDxxxx(RF)RB | Copyright 2013 | HINGE SIDE | DCLK_RST | EXT CLK | EXT_TRIG | SILKSCREEN, TOP SIDE | 12V
GND1: L2_GND1
SIG1: L3_SIG1
PWR1: L4_PWR1
GND2: L5_GND2
SIG2: L6_SIG2
PWR2: L7_PWR2
SIG3: L8_SIG3
GND3: L9_GND3
COMPVAL_TYPE_TOP: J12 SLOT DIMENSIONS | 13. COPPER THIEVING PATTERN MAY BE ADDED ON LAYERS 1 AND 10 FOR PLATING UNIFORMITY. | 14. BOARD MUST HAVE RoHS CERTIFICATE. | SOLDERMASK MAY BE MODIFIED TO HELP PREVENT BRIDGING ON FINE PITCH DEVICES.
USER_PART_NUM_TOP: FIGURE | SIZE | 9.84 | 10.0 | 13.0 | 31.0 | 36.0 | 37.0 | 40.0 | 51.0 | 59.0 | 60.0 | 65.0 | 70.0 | 92.0 | 106.0 | 120.0 | 125.0 | 78.0 | 64.0x36.0 | DRILL CHART: TOP to BOTTOM | ALL UNITS ARE IN MILS | PLATED | NON-PLATED | QTY | 351 | 25 | 1356 | 569 | 2 | 67 | 10 | 65 | 24 | 3 | 1 | 4 | 5
